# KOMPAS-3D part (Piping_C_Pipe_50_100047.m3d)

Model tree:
1. Plane XY
2. Plane ZX
3. Plane ZY
4. X Axis
5. Y Axis
6. Z Axis
7. Origin
8. Path  (labels: Отвод 90 Dy 50; Труба Dy 50; Тройник Dy 50)
9. Plane of section
10. Section of pipe
11. Pipe
     Толщина стенки 1 = 1

Referenced files in C:\Program Files\ASCON\KOMPAS-3D V10\Libs\Piping\Models\Tanks\: Tanks.a3d
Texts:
  Pipe Dn 50
  Steel ASTM A295
  Three Point Plane
  Plane at Angle
  Line and Point Plane
  Axis through Two Vertices
  Axis of Feature
  Axis of Conical Surface
  Axis through Edge
  Приклеить элемент выдавливания
  Приклеить элемент вращения
  Приклеить кинематический элемент
  Приклеить элемент по сечениям
  Trim by Surface
  Trim by Sketch
  Feature with No History
  Intersection Axis of Two Planes
  Two Line Plane
  Line and Face Plane
  Bend by line
  Hole in sheet body
  Cut in sheet body
  Point in CM
  Linear Dimension from Line to Point
  Surface Finish Symbol
  Geometric Tolerance Symbol
  Текст на чертеже
  Линия-выноска #1
  Линия-выноска #2
  Линия-выноска #3
  Отклонения формы и база
  Марка координационной оси
  Марка/позиционное обозначение с линией-выноской
  Марка/позиционное обозначение на линии
  Марка/позиционное обозначение без линии-выноски
  Отвод 90 Dy 50
  Труба Dy 50
  Тройник Dy 50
